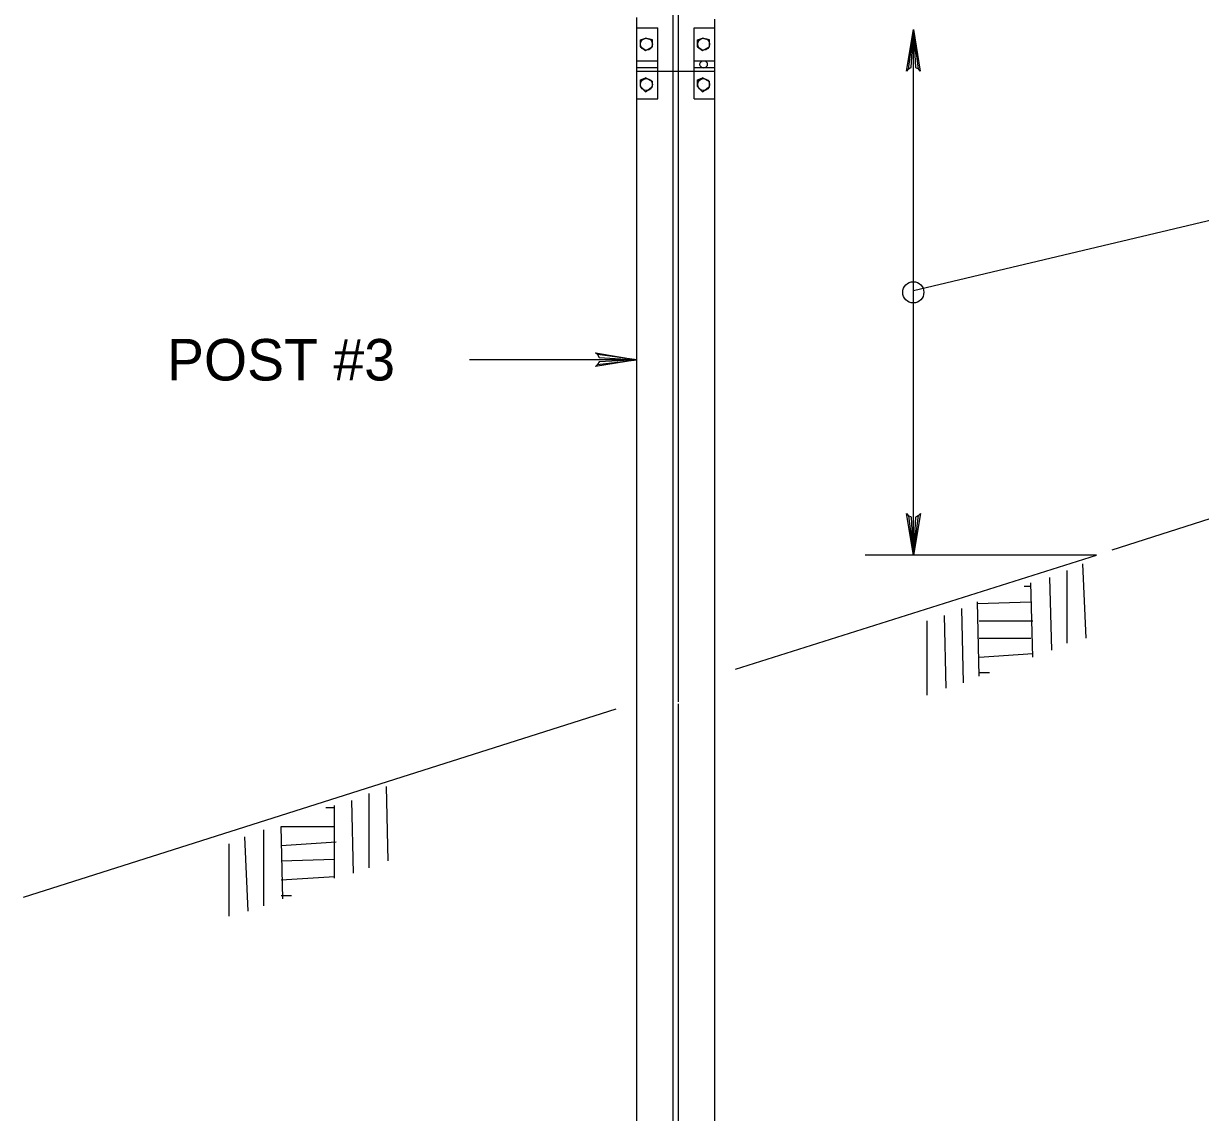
# Model space of a CAD drawing. Extents: x 637580 to 641008, y 294594 to 295782.
# Drawn here: x 638084.3 to 638169.4, y 295470.8 to 295549.6 of the extents above; entities that cross this region are included whole.
import ezdxf

# ---------------------------------------------------------------- set-up
doc = ezdxf.new("R2010")
doc.units = 0
for name, color, linetype in [('1', 7, 'Continuous'), ('2', 7, 'Continuous'), ('3', 7, 'Continuous')]:
    doc.layers.add(name, color=color, linetype=linetype)

# ---------------------------------------------------------------- blocks, each defined once
blk = doc.blocks.new('RARROW')
at = {"layer": '3'}
blk.add_lwpolyline([(-2.2695, 0.285), (-2.184875, 0.12075), (0, 0), (-2.2695, 0.285), (-2.38575, 0.384625), (0, 0), (-2.183125, -0.108), (-2.262875, -0.2705), (0, 0), (-2.38575, -0.379125), (-2.262875, -0.2705)], dxfattribs=at)

msp = doc.modelspace()

# ---------------------------------------------------------------- linework, layer by layer
at = {"layer": '1'}
for p, q in [((638148.687, 295530.251), (638222.812, 295547.876)), ((638159.812, 295504.751), (638159.812, 295510.001)), ((638161.187, 295505.126), (638160.937, 295510.501)), ((638156.687, 295508.876), (638157.187, 295508.876)), ((638157.312, 295503.751), (638157.187, 295509.126)), ((638158.687, 295504.251), (638158.562, 295509.501)), ((638152.312, 295501.876), (638152.187, 295507.251)), ((638153.312, 295507.626), (638157.187, 295507.751)), ((638153.437, 295502.376), (638153.312, 295507.751)), ((638149.687, 295501.001), (638149.687, 295506.376)), ((638151.062, 295501.501), (638150.937, 295506.751)), ((638153.437, 295506.376), (638157.312, 295506.376)), ((638153.437, 295505.126), (638157.187, 295505.126)), ((638153.437, 295503.751), (638157.312, 295504.001)), ((638153.437, 295502.626), (638154.187, 295502.626)), ((638110.687, 295489.001), (638110.562, 295494.376)), ((638109.312, 295488.501), (638109.312, 295493.876)), ((638106.187, 295492.876), (638106.812, 295492.876)), ((638106.812, 295487.751), (638106.812, 295493.001)), ((638108.187, 295488.126), (638108.062, 295493.376)), ((638101.687, 295485.751), (638101.687, 295491.251)), ((638102.937, 295491.501), (638106.812, 295491.501)), ((638103.062, 295486.251), (638102.937, 295491.501)), ((638099.187, 295485.001), (638099.187, 295490.251)), ((638100.562, 295485.376), (638100.312, 295490.751)), ((638102.937, 295490.126), (638106.937, 295490.376)), ((638102.937, 295489.001), (638106.812, 295489.126)), ((638102.937, 295487.626), (638106.812, 295487.876)), ((638102.937, 295486.501), (638103.687, 295486.501))]:
    msp.add_line(p, q, dxfattribs=at)
msp.add_ellipse((638148.672, 295530.126), major_axis=(0, -0.768), ratio=0.996388, dxfattribs=at)
at = {"layer": '2'}
for p, q in [((638131.312, 295500.376), (638131.312, 295703.001)), ((638131.687, 295500.501), (638131.687, 295703.001)), ((638128.687, 295434.626), (638128.687, 295550.001)), ((638134.312, 295434.626), (638134.312, 295549.876)), ((638128.687, 295549.251), (638130.187, 295549.251)), ((638130.187, 295544.126), (638130.187, 295549.251)), ((638132.812, 295549.251), (638134.312, 295549.251)), ((638132.812, 295544.126), (638132.812, 295549.251)), ((638148.687, 295511.126), (638148.687, 295549.126)), ((638128.937, 295548.376), (638129.312, 295548.501)), ((638128.937, 295548.376), (638129.312, 295548.501)), ((638128.937, 295547.876), (638128.937, 295548.376)), ((638128.937, 295547.876), (638128.937, 295548.376)), ((638129.312, 295548.501), (638129.812, 295548.376)), ((638129.812, 295548.376), (638129.312, 295548.501)), ((638129.312, 295548.126), (638129.312, 295548.126)), ((638129.812, 295547.876), (638129.812, 295548.376)), ((638129.812, 295547.876), (638129.812, 295548.376)), ((638133.062, 295548.376), (638133.437, 295548.501)), ((638133.062, 295548.376), (638133.437, 295548.501)), ((638133.062, 295547.876), (638133.062, 295548.376)), ((638133.062, 295547.876), (638133.062, 295548.376)), ((638133.437, 295548.501), (638133.937, 295548.376)), ((638133.937, 295548.376), (638133.437, 295548.501)), ((638133.437, 295548.126), (638133.437, 295548.126)), ((638133.937, 295547.876), (638133.937, 295548.376)), ((638133.937, 295547.876), (638133.937, 295548.376)), ((638128.937, 295547.876), (638129.312, 295547.626)), ((638129.312, 295547.626), (638128.937, 295547.876)), ((638129.312, 295547.626), (638129.812, 295547.876)), ((638129.312, 295547.626), (638129.812, 295547.876)), ((638133.062, 295547.876), (638133.437, 295547.626)), ((638133.437, 295547.626), (638133.062, 295547.876)), ((638133.437, 295547.626), (638133.937, 295547.876)), ((638133.437, 295547.626), (638133.937, 295547.876)), ((638128.687, 295546.876), (638130.187, 295546.876)), ((638128.687, 295546.376), (638130.187, 295546.376)), ((638132.812, 295546.876), (638134.312, 295546.876)), ((638132.812, 295546.376), (638134.312, 295546.376)), ((638133.437, 295546.751), (638133.437, 295546.751)), ((638128.687, 295546.126), (638128.687, 295546.126)), ((638128.687, 295546.126), (638128.687, 295546.126)), ((638128.687, 295546.126), (638130.187, 295546.126)), ((638128.687, 295546.126), (638128.687, 295546.126)), ((638128.937, 295545.501), (638129.312, 295545.626)), ((638128.937, 295545.376), (638129.312, 295545.626)), ((638128.937, 295545.001), (638128.937, 295545.501)), ((638129.312, 295545.626), (638129.812, 295545.376)), ((638129.812, 295545.376), (638129.312, 295545.626)), ((638130.187, 295546.126), (638132.812, 295546.126)), ((638132.812, 295546.126), (638134.312, 295546.126)), ((638133.062, 295545.501), (638133.437, 295545.626)), ((638133.062, 295545.376), (638133.437, 295545.626)), ((638133.062, 295545.001), (638133.062, 295545.501)), ((638133.437, 295545.626), (638133.937, 295545.376)), ((638133.937, 295545.376), (638133.437, 295545.626)), ((638128.937, 295545.001), (638128.937, 295545.376)), ((638128.937, 295545.001), (638129.312, 295544.626)), ((638129.312, 295544.626), (638128.937, 295545.001)), ((638129.312, 295545.251), (638129.312, 295545.251)), ((638129.312, 295544.626), (638129.812, 295545.001)), ((638129.312, 295544.626), (638129.812, 295545.001)), ((638129.812, 295545.001), (638129.812, 295545.376)), ((638129.812, 295545.001), (638129.812, 295545.376)), ((638133.062, 295545.001), (638133.062, 295545.376)), ((638133.062, 295545.001), (638133.437, 295544.626)), ((638133.437, 295544.626), (638133.062, 295545.001)), ((638133.437, 295545.251), (638133.437, 295545.251)), ((638133.437, 295544.626), (638133.937, 295545.001)), ((638133.437, 295544.626), (638133.937, 295545.001)), ((638133.937, 295545.001), (638133.937, 295545.376)), ((638133.937, 295545.001), (638133.937, 295545.376)), ((638128.687, 295544.126), (638130.187, 295544.126)), ((638132.812, 295544.126), (638134.312, 295544.126)), ((638163.062, 295511.501), (638219.562, 295529.626)), ((638128.687, 295525.251), (638116.562, 295525.251)), ((638131.687, 295521.751), (638131.687, 295521.751)), ((638135.812, 295502.876), (638161.937, 295511.126)), ((638161.937, 295511.126), (638145.187, 295511.126)), ((638131.312, 295427.251), (638131.312, 295500.376)), ((638131.687, 295427.251), (638131.687, 295500.376)), ((638084.312, 295486.376), (638127.187, 295500.001))]:
    msp.add_line(p, q, dxfattribs=at)
for centre, major_axis in [((638129.373, 295548.071), (0, -0.432)), ((638133.509, 295548.071), (0, -0.432)), ((638133.509, 295546.611), (0, 0.265)), ((638129.373, 295545.153), (0, -0.432)), ((638133.509, 295545.153), (0, -0.432))]:
    msp.add_ellipse(centre, major_axis=major_axis, ratio=0.996388, dxfattribs=at)

# ---------------------------------------------------------------- block references
at = {"layer": '2', "xscale": 1.2574347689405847, "yscale": 1.3092961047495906}
for p, rotation in [((638148.687, 295549.126), 89.99999999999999), ((638148.687, 295511.126), -90.00000000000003)]:
    msp.add_blockref('RARROW', p, dxfattribs=dict(at, rotation=rotation))
msp.add_blockref('RARROW', (638128.687, 295525.251), dxfattribs=at)

# ---------------------------------------------------------------- texts
at = {"layer": '3'}
msp.add_text('POST #3', height=3, dxfattribs=at).set_placement((638094.687, 295523.751))

doc.saveas('drawing.dxf')
